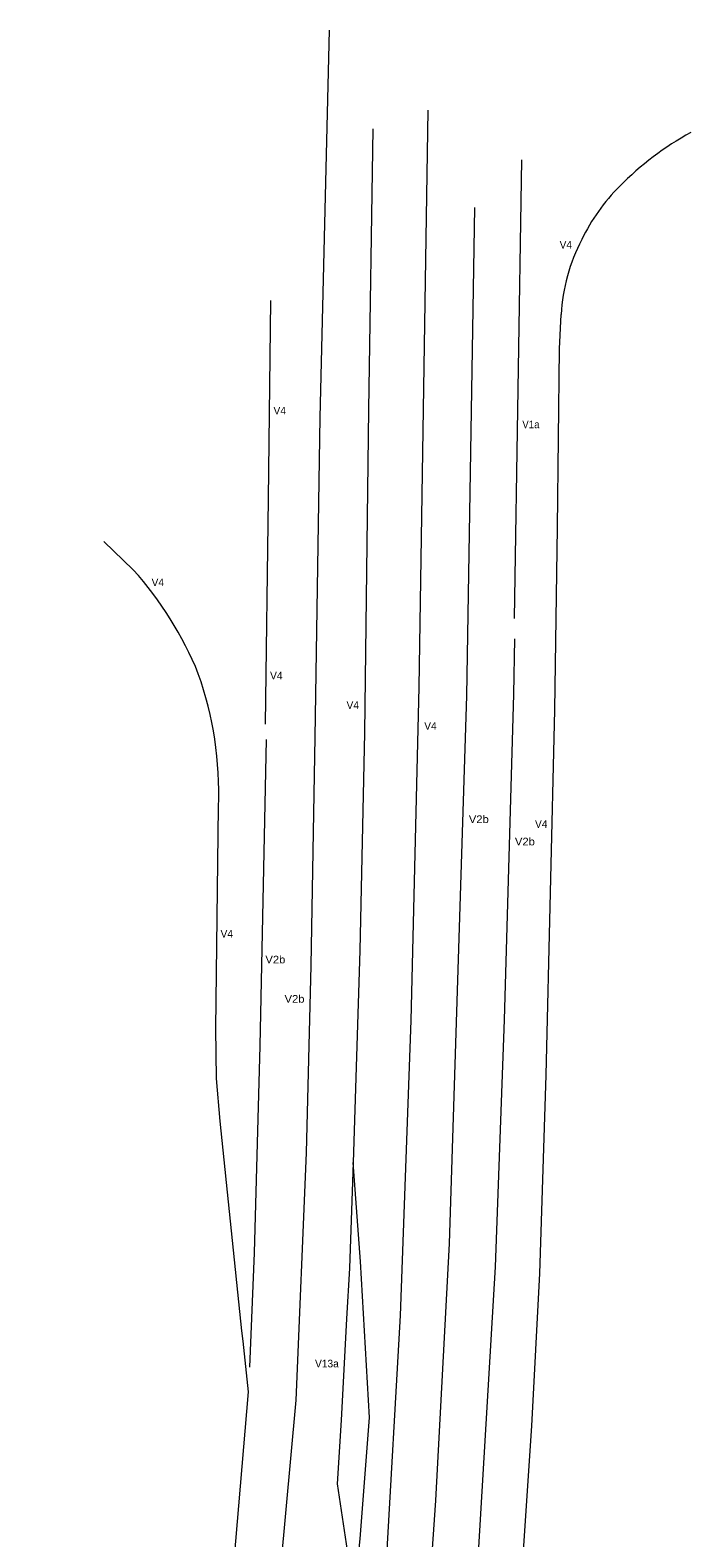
# Model space of a CAD drawing. Extents: x -598770 to -598612, y -1162818 to -1162391.
# Drawn here: x -598685.2 to -598633.2, y -1162510.2 to -1162391.3 of the extents above; entities that cross this region are included whole.
import ezdxf

# ---------------------------------------------------------------- set-up
doc = ezdxf.new("R2010")
doc.units = 0
doc.header["$LTSCALE"] = 0.24
doc.layers.add('47', color=7, linetype='Continuous', lineweight=13)

msp = doc.modelspace()

# ---------------------------------------------------------------- linework, layer by layer
at = {"layer": '47'}
for p, q in [((-598647.04, -1162437.7), (-598646.46, -1162401.56)), ((-598677.06, -1162433.86), (-598679.38, -1162431.63))]:
    msp.add_line(p, q, dxfattribs=at)
for points in [[(-598678.87, -1162592.39), (-598677.52, -1162586.33), (-598673.52, -1162568.4), (-598671.82, -1162559.94), (-598670.41, -1162551.33), (-598668.56, -1162538.37), (-598666.59, -1162522.8), (-598665.43, -1162512.51), (-598664.23, -1162499.31), (-598663.42, -1162479.81), (-598663.05, -1162465.06), (-598662.73, -1162447.04), (-598662.35, -1162421.85), (-598661.61, -1162391.33)], [(-598679.49, -1162630.64), (-598677.61, -1162624.52), (-598674.71, -1162614.13), (-598672.49, -1162605.39), (-598669.14, -1162591.74), (-598666.82, -1162580.97), (-598664.07, -1162567.02), (-598662.23, -1162555.94), (-598659.99, -1162540.04), (-598658.35, -1162525.71), (-598657.15, -1162512.49), (-598656.01, -1162492.63), (-598655.18, -1162469.38), (-598654.56, -1162443.12), (-598653.84, -1162397.63)], [(-598658.2, -1162399.11), (-598658.55, -1162421.23), (-598658.85, -1162446.7), (-598659.22, -1162463.86), (-598659.74, -1162480.57)], [(-598685.18, -1162659.01), (-598682.44, -1162650.81), (-598678.78, -1162639.81), (-598676.01, -1162631.49), (-598669.81, -1162609.43), (-598665.71, -1162592.63), (-598660.52, -1162567.28), (-598657.82, -1162550.24), (-598655.55, -1162533.08), (-598653.64, -1162512.9), (-598653.24, -1162507.21), (-598652.17, -1162486.96), (-598650.81, -1162443.8), (-598650.17, -1162405.3)], [(-598666.65, -1162446.02), (-598666.42, -1162428.26), (-598666.24, -1162412.64)], [(-598646.54, -1162514.33), (-598645.68, -1162501.34), (-598645.05, -1162489.31), (-598644.56, -1162473.7), (-598643.88, -1162444.91), (-598643.66, -1162430.52), (-598643.5, -1162416.45), (-598643.38, -1162413.74)], [(-598647.05, -1162439.3), (-598647.13, -1162443.65), (-598647.86, -1162469.34), (-598648.56, -1162488.8), (-598650.03, -1162513.56), (-598651.56, -1162529.37), (-598652.75, -1162539.5), (-598655.24, -1162557.05), (-598657.58, -1162570.89), (-598660.39, -1162585.19), (-598664.32, -1162602.18), (-598668.6, -1162619.03), (-598670.31, -1162624.74)], [(-598667.89, -1162496.7), (-598667.51, -1162487.68), (-598667.08, -1162471.37), (-598666.58, -1162447.23)], [(-598669.23, -1162513.32), (-598669.13, -1162511.96), (-598667.99, -1162498.64), (-598668.42, -1162494.66), (-598668.51, -1162493.83), (-598670.21, -1162477.32), (-598670.5, -1162473.95), (-598670.55, -1162470), (-598670.35, -1162452.54)]]:
    msp.add_lwpolyline(points, dxfattribs=at)
msp.add_lwpolyline([(-598659.74, -1162480.57), (-598660.04, -1162488.91), (-598660.27, -1162492.9), (-598660.68, -1162500.88), (-598661.01, -1162505.9), (-598660.06, -1162512.2), (-598659.7, -1162515.17), (-598659.2, -1162510.24), (-598658.47, -1162500.66), (-598659.18, -1162488.38)], close=True, dxfattribs=at)
for centre, radius, start, end in [((-598621.6989, -1162420.3957), 23.9202, 118.62922, 135.53426), ((-598628.0504, -1162414.403), 15.1905, 134.88426, 154.40253), ((-598628.559, -1162414.6595), 14.8495, 152.66206, 176.45005), ((-598697.9515, -1162452.6158), 28.0755, 22.10679, 41.91655), ((-598698.4677, -1162451.4364), 28.1393, 357.75229, 19.48548)]:
    msp.add_arc(centre, radius, start, end, dxfattribs=at)

# ---------------------------------------------------------------- texts
for s, p in [('V4', (-598643.49, -1162408.54)), ('V4', (-598666.02, -1162421.62)), ('V4', (-598675.62, -1162435.15)), ('V4', (-598666.29, -1162442.5)), ('V4', (-598660.27, -1162444.83)), ('V4', (-598654.15, -1162446.47)), ('V4', (-598645.43, -1162454.2)), ('V4', (-598670.19, -1162462.85)), ('V13a', (-598662.75, -1162496.72))]:
    msp.add_text(s, height=0.6, dxfattribs=at).set_placement(p)
for s, width, p in [('V1a', 0.95, (-598646.43, -1162422.7)), ('V2b', 1.1, (-598650.64, -1162453.82)), ('V2b', 1.1, (-598647.01, -1162455.58)), ('V2b', 1.1, (-598666.66, -1162464.88)), ('V2b', 1.1, (-598665.15, -1162467.98))]:
    msp.add_text(s, height=0.6, dxfattribs=dict(at, width=width)).set_placement(p)

doc.saveas('drawing.dxf')
